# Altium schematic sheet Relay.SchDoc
size A4; Organization: Altium Limited; Address1: L3, 12a Rodborough Rd; Address2: Frenchs Forest; Address3: NSW; Address4: Australia 2086
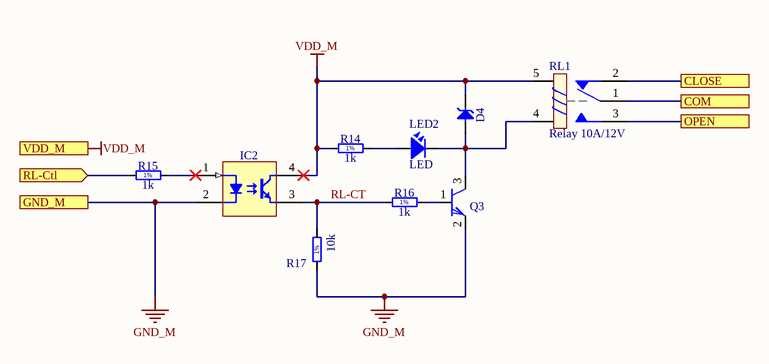
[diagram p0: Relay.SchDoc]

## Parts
D4  BZG03C220  [DIOM5326X230N]  (value not drawn)
IC2  SFH6156-4  [SOIC254P977X406-4N]  (value not drawn)
LED2  LED  [L-0805]
Q3  C1815  [SOT23-3]  (value not drawn)
R14  1k  [RESC1608X55N]
R15  1k  [RESC1608X55N]
R16  1k  [RESC1608X55N]
R17  10k  [RESC1608X55N]
RL1  Relay 10A/12V  [RL_SPDT_10A]

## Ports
CLOSE, COM, GND_M, OPEN, RL-Ctl (in), VDD_M

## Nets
GND_M: IC2.2(C) Q3.2(E) R17.1 ; port GND_M
VDD_M: D4.1(C) IC2.4(C) R14.1 RL1.5 ; port VDD_M
CLOSE: RL1.2 ; port CLOSE
COM: RL1.1 ; port COM
OPEN: RL1.3 ; port OPEN
RL-CT: IC2.3(E) R16.1 R17.2
RL-Ctl: R15.1 ; port RL-Ctl
NetD4_2: D4.2(A) LED2.2 Q3.3(C) RL1.4
NetIC2_1: IC2.1(A) R15.2
NetLED2_1: LED2.1 R14.2
NetQ3_1: Q3.1(B) R16.2

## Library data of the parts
D4 = BZG03C220: Zener Diode; Part Description: Voltage Regulator Diode; Manufacturer: VISHAY SEMICONDUCTOR; Voltage: 220V; Power: 1.25W; Table: Diodes
IC2 = SFH6156-4: Single Optocoupler; Part Description: Optocoupler, Phototransistor Output, High Reliability, 5300 VRMS; Manufacturer: VISHAY SEMICONDUCTORS; Table: Optocouplers
LED2 = LED: LED Single colour Green and Red; Value: LED 3 ly Single Colour
Q3 = 2SC1815: PSpiceTemplate: Q^@REFDES %c %b %e @MODEL; Vendor: Digikey
R14 R16 = R0603_200R_1%_0.1W_100PPM: Resistor - 1%; Part Description: General Purpose Thick Film Chip Resistor; Manufacturer: GENERIC; Manufacturer1 Part Number: NRC06F2000TRF; Value: 200; Power: 0.1W; TC: ±100ppm/°C; Table: Resistors SMD
R15 = R0603_1K_1%_0.1W_100PPM: Resistor - 1%; Part Description: General Purpose Thick Film Chip Resistor; Manufacturer: GENERIC; Manufacturer1 Part Number: NRC06F1001TRF; Power: 0.1W; TC: ±100ppm/°C; Table: Resistors SMD
R17 = R0603_10K_1%_0.1W_100PPM: Resistor - 1%; Part Description: General Purpose Thick Film Chip Resistor; Manufacturer: GENERIC; Manufacturer1 Part Number: NRC06F1002TRF; Power: 0.1W; TC: ±100ppm/°C; Table: Resistors SMD
RL1 = Relay 1: Relay SPDT,10A - 12VDC 5 Pin; Value: Relay SPDT, 10A, 12V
